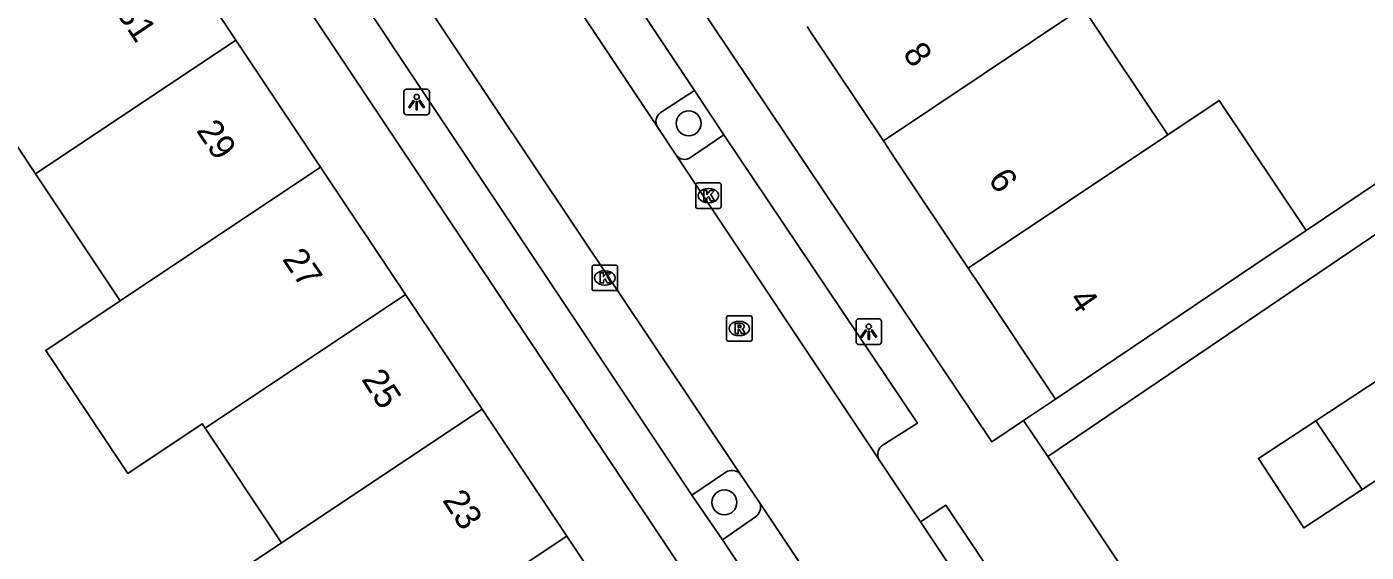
# Model space of a CAD drawing. Extents: x 158352 to 159489, y 383828 to 384597.
# Drawn here: x 158720.9 to 158773.4, y 384288.8 to 384309.4 of the extents above; entities that cross this region are included whole.
import ezdxf

# ---------------------------------------------------------------- set-up
doc = ezdxf.new("R2010")
doc.units = 0
for name, color, linetype in [('IMGEO_Boom', 7, 'Continuous'), ('IMGEO_Kolk', 7, 'Continuous'), ('IMGEO_Lichtpunt', 7, 'Continuous'), ('IMGEO_Pand', 7, 'Continuous'), ('IMGEO_Pand_nummerreeks', 7, 'Continuous'), ('IMGEO_Parkeervlak_open', 7, 'Continuous'), ('IMGEO_Rijbaan_lokaal_open', 7, 'Continuous'), ('IMGEO_Rioolput', 7, 'Continuous'), ('IMGEO_Voetpad_open', 7, 'Continuous')]:
    doc.layers.add(name, color=color, linetype=linetype)

msp = doc.modelspace()

# ---------------------------------------------------------------- linework, layer by layer
at = {"layer": 'IMGEO_Boom'}
for centre in [(158746.856, 384305.642), (158748.26, 384290.777)]:
    msp.add_circle(centre, 0.489, dxfattribs=at)
at = {"layer": 'IMGEO_Kolk'}
for p, q in [((158747.131, 384302.381), (158747.131, 384303.233)), ((158747.206, 384303.307), (158748.058, 384303.307)), ((158747.619, 384303.087), (158747.644, 384303.087)), ((158748.132, 384303.233), (158748.132, 384302.381)), ((158747.642, 384302.527), (158747.617, 384302.527)), ((158748.058, 384302.307), (158747.206, 384302.307)), ((158743.067, 384299.155), (158743.067, 384300.007)), ((158743.142, 384300.081), (158743.994, 384300.081)), ((158743.555, 384299.861), (158743.58, 384299.861)), ((158744.068, 384300.007), (158744.068, 384299.155)), ((158743.578, 384299.301), (158743.553, 384299.301)), ((158743.994, 384299.081), (158743.142, 384299.081))]:
    msp.add_line(p, q, dxfattribs=at)
for points in [[(158747.131, 384302.381), (158747.131, 384303.233)], [(158747.206, 384303.307), (158748.058, 384303.307)], [(158747.452, 384303.007), (158747.575, 384303.007), (158747.575, 384302.856), (158747.705, 384303.007), (158747.869, 384303.007), (158747.723, 384302.856), (158747.876, 384302.607), (158747.724, 384302.607), (158747.639, 384302.771), (158747.575, 384302.704), (158747.575, 384302.607), (158747.452, 384302.607), (158747.452, 384303.007)], [(158748.132, 384303.233), (158748.132, 384302.381)], [(158748.058, 384302.307), (158747.206, 384302.307)], [(158743.067, 384299.155), (158743.067, 384300.007)], [(158743.142, 384300.081), (158743.994, 384300.081)], [(158743.388, 384299.781), (158743.511, 384299.781), (158743.511, 384299.63), (158743.641, 384299.781), (158743.805, 384299.781), (158743.659, 384299.63), (158743.812, 384299.381), (158743.66, 384299.381), (158743.575, 384299.545), (158743.511, 384299.478), (158743.511, 384299.381), (158743.388, 384299.381), (158743.388, 384299.781)], [(158744.068, 384300.007), (158744.068, 384299.155)], [(158743.994, 384299.081), (158743.142, 384299.081)]]:
    msp.add_lwpolyline(points, dxfattribs=at)
for centre, start, end in [((158747.208, 384303.231), 91.552, 178.448), ((158747.208, 384303.231), 91.552, 178.448), ((158748.056, 384303.231), 1.552, 88.448), ((158748.056, 384303.231), 1.552, 88.448), ((158747.208, 384302.383), 181.552, 268.448), ((158747.208, 384302.383), 181.552, 268.448), ((158748.056, 384302.383), 271.552, 358.448), ((158748.056, 384302.383), 271.552, 358.448), ((158743.144, 384300.005), 91.552, 178.448), ((158743.144, 384300.005), 91.552, 178.448), ((158743.992, 384300.005), 1.552, 88.448), ((158743.992, 384300.005), 1.552, 88.448), ((158743.144, 384299.157), 181.552, 268.448), ((158743.144, 384299.157), 181.552, 268.448), ((158743.992, 384299.157), 271.552, 358.448), ((158743.992, 384299.157), 271.552, 358.448)]:
    msp.add_arc(centre, 0.0765, start, end, dxfattribs=at)
for centre, major_axis, ratio, start_param, end_param in [((158747.618, 384302.807), (-0.387, 0.002), 0.722429, 4.712389, 7.853982), ((158747.643, 384302.807), (-0.39, 0.002), 0.717154, 1.570796, 4.712389), ((158743.554, 384299.581), (-0.387, 0.002), 0.722429, 4.712389, 7.853982), ((158743.579, 384299.581), (-0.39, 0.002), 0.717154, 1.570796, 4.712389)]:
    msp.add_ellipse(centre, major_axis=major_axis, ratio=ratio, start_param=start_param, end_param=end_param, dxfattribs=at)
at = {"layer": 'IMGEO_Lichtpunt'}
for p, q in [((158735.688, 384306.881), (158735.688, 384306.074)), ((158735.688, 384306.881), (158735.688, 384306.074)), ((158736.59, 384306.976), (158735.782, 384306.976)), ((158736.59, 384306.976), (158735.782, 384306.976)), ((158736.684, 384306.074), (158736.684, 384306.881)), ((158736.684, 384306.074), (158736.684, 384306.881)), ((158735.782, 384305.98), (158736.59, 384305.98)), ((158735.782, 384305.98), (158736.59, 384305.98)), ((158753.424, 384297.875), (158753.424, 384297.068)), ((158753.424, 384297.875), (158753.424, 384297.068)), ((158754.326, 384297.97), (158753.518, 384297.97)), ((158754.326, 384297.97), (158753.518, 384297.97)), ((158754.42, 384297.068), (158754.42, 384297.875)), ((158754.42, 384297.068), (158754.42, 384297.875)), ((158753.518, 384296.974), (158754.326, 384296.974)), ((158753.518, 384296.974), (158754.326, 384296.974))]:
    msp.add_line(p, q, dxfattribs=at)
for points in [[(158736.062, 384306.545), (158736.101, 384306.517), (158735.913, 384306.255), (158735.875, 384306.282), (158736.062, 384306.545)], [(158736.274, 384306.517), (158736.312, 384306.544), (158736.499, 384306.282), (158736.46, 384306.254), (158736.274, 384306.517)], [(158736.164, 384306.497), (158736.211, 384306.497), (158736.211, 384306.175), (158736.164, 384306.175), (158736.164, 384306.497)], [(158753.798, 384297.539), (158753.837, 384297.511), (158753.649, 384297.249), (158753.611, 384297.276), (158753.798, 384297.539)], [(158753.9, 384297.491), (158753.947, 384297.491), (158753.947, 384297.169), (158753.9, 384297.169), (158753.9, 384297.491)], [(158754.01, 384297.511), (158754.048, 384297.538), (158754.235, 384297.276), (158754.196, 384297.248), (158754.01, 384297.511)]]:
    msp.add_lwpolyline(points, dxfattribs=at)
for centre in [(158736.187, 384306.679), (158753.923, 384297.673)]:
    msp.add_circle(centre, 0.0994, dxfattribs=at)
for centre, start, end in [((158735.782, 384306.881), 90, 180), ((158735.782, 384306.881), 90, 180), ((158736.59, 384306.881), 0, 90), ((158736.59, 384306.881), 0, 90), ((158735.782, 384306.074), 180, 270), ((158735.782, 384306.074), 180, 270), ((158736.59, 384306.074), 270, 0), ((158736.59, 384306.074), 270, 360), ((158753.518, 384297.875), 90, 180), ((158753.518, 384297.875), 90, 180), ((158754.326, 384297.875), 0, 90), ((158754.326, 384297.875), 0, 90), ((158753.518, 384297.068), 180, 270), ((158753.518, 384297.068), 180, 270), ((158754.326, 384297.068), 270, 0), ((158754.326, 384297.068), 270, 360)]:
    msp.add_arc(centre, 0.0946, start, end, dxfattribs=at)
at = {"layer": 'IMGEO_Pand'}
for points in [[(158729.096, 384308.902), (158726.098, 384313.399)], [(158754.497, 384304.952), (158762.322, 384310.18)], [(158762.322, 384310.18), (158762.786, 384309.485), (158763.459, 384308.478), (158765.656, 384305.19)], [(158754.497, 384304.952), (158751.64, 384309.236), (158751.501, 384309.445)], [(158721.235, 384303.662), (158729.096, 384308.902)], [(158732.416, 384303.922), (158729.096, 384308.902)], [(158718.236, 384308.158), (158721.235, 384303.662)], [(158765.656, 384305.19), (158767.669, 384306.535), (158771.074, 384301.44)], [(158765.656, 384305.19), (158757.826, 384299.96)], [(158757.826, 384299.96), (158754.961, 384304.256), (158754.497, 384304.952)], [(158732.416, 384303.922), (158724.556, 384298.683)], [(158735.745, 384298.927), (158732.416, 384303.922)], [(158724.556, 384298.683), (158721.235, 384303.662)], [(158771.074, 384301.44), (158769.065, 384300.088), (158761.248, 384294.829)], [(158761.248, 384294.829), (158758.282, 384299.276), (158757.826, 384299.96)], [(158724.556, 384298.683), (158721.636, 384296.735), (158724.854, 384291.911), (158727.774, 384293.858), (158727.887, 384293.689)], [(158735.745, 384298.927), (158727.887, 384293.689)], [(158738.751, 384294.436), (158735.745, 384298.927)], [(158771.454, 384293.979), (158773.978, 384295.637), (158775.767, 384292.914), (158773.276, 384291.278)], [(158730.885, 384289.193), (158738.751, 384294.436)], [(158742.072, 384289.458), (158738.751, 384294.436)], [(158773.276, 384291.278), (158770.991, 384289.777), (158769.202, 384292.5), (158771.454, 384293.979)], [(158771.454, 384293.979), (158773.276, 384291.278)], [(158727.887, 384293.689), (158730.885, 384289.193)], [(158742.072, 384289.458), (158734.206, 384284.214)], [(158745.403, 384284.464), (158742.072, 384289.458)], [(158730.885, 384289.193), (158727.536, 384286.959), (158730.857, 384281.98), (158734.206, 384284.214)]]:
    msp.add_lwpolyline(points, dxfattribs=at)
at = {"layer": 'IMGEO_Parkeervlak_open'}
for points in [[(158747.086, 384306.935), (158745.743, 384306.049)], [(158746.928, 384304.308), (158748.237, 384305.189)], [(158746.983, 384291.062), (158748.314, 384291.963)], [(158748.187, 384289.313), (158749.479, 384290.214)]]:
    msp.add_lwpolyline(points, dxfattribs=at)
for centre, radius, start, end in [((158745.981, 384305.718), 0.407, 125.7199, 209.4283), ((158746.691, 384304.624), 0.395, 214.8862, 306.8855), ((158748.557, 384291.554), 0.476, 49.3617, 120.7167), ((158749.226, 384290.589), 0.452, 303.9569, 18.1768)]:
    msp.add_arc(centre, radius, start, end, dxfattribs=at)
at = {"layer": 'IMGEO_Rijbaan_lokaal_open'}
for points in [[(158745.626, 384305.518), (158731.636, 384326.508)], [(158748.867, 384291.915), (158732.619, 384316.209)], [(158745.626, 384305.518), (158746.367, 384304.398)], [(158746.367, 384304.398), (158754.327, 384292.451)], [(158754.327, 384292.451), (158755.951, 384290.012)], [(158749.656, 384290.73), (158748.867, 384291.915)], [(158765.371, 384267.168), (158749.656, 384290.73)], [(158755.951, 384290.012), (158759.379, 384284.871)]]:
    msp.add_lwpolyline(points, dxfattribs=at)
at = {"layer": 'IMGEO_Rioolput'}
for p, q in [((158748.34, 384297.169), (158748.34, 384298.021)), ((158748.415, 384298.095), (158749.267, 384298.095)), ((158748.828, 384297.875), (158748.853, 384297.875)), ((158749.341, 384298.021), (158749.341, 384297.169)), ((158749.267, 384297.095), (158748.415, 384297.095)), ((158748.851, 384297.315), (158748.826, 384297.315))]:
    msp.add_line(p, q, dxfattribs=at)
for points in [[(158748.34, 384297.169), (158748.34, 384298.021)], [(158748.415, 384298.095), (158749.267, 384298.095)], [(158748.929, 384297.793), (158748.677, 384297.795), (158748.677, 384297.395)], [(158748.855, 384297.714), (158748.801, 384297.714), (158748.801, 384297.633)], [(158748.801, 384297.633), (158748.853, 384297.633)], [(158749.341, 384298.021), (158749.341, 384297.169)], [(158749.267, 384297.095), (158748.415, 384297.095)], [(158748.677, 384297.395), (158748.801, 384297.395), (158748.801, 384297.557), (158748.812, 384297.557)], [(158748.859, 384297.528), (158748.93, 384297.395), (158749.07, 384297.395), (158749.005, 384297.521)]]:
    msp.add_lwpolyline(points, dxfattribs=at)
for centre, radius, start, end in [((158748.417, 384298.019), 0.0765, 91.552, 178.448), ((158748.417, 384298.019), 0.0765, 91.552, 178.448), ((158748.837, 384297.822), 0.19, 274.7715, 282.9687), ((158748.861, 384297.618), 0.0964, 77.0061, 93.1865), ((158748.875, 384297.675), 0.0378, 276.6634, 79.6772), ((158748.928, 384297.683), 0.109, 350.3612, 89.416), ((158748.926, 384297.683), 0.112, 277.5842, 350.9817), ((158749.265, 384298.019), 0.0765, 1.552, 88.448), ((158749.265, 384298.019), 0.0765, 1.552, 88.448), ((158748.417, 384297.171), 0.0765, 181.552, 268.448), ((158748.417, 384297.171), 0.0765, 181.552, 268.448), ((158748.811, 384297.504), 0.0533, 26.0293, 88.6989), ((158748.91, 384297.468), 0.108, 29.5134, 73.7905), ((158749.265, 384297.171), 0.0765, 271.552, 358.448), ((158749.265, 384297.171), 0.0765, 271.552, 358.448)]:
    msp.add_arc(centre, radius, start, end, dxfattribs=at)
for centre, major_axis, ratio, start_param, end_param in [((158748.827, 384297.595), (-0.387, 0.002), 0.722429, 4.712389, 7.853982), ((158748.852, 384297.595), (-0.39, 0.002), 0.717154, 1.570796, 4.712389)]:
    msp.add_ellipse(centre, major_axis=major_axis, ratio=ratio, start_param=start_param, end_param=end_param, dxfattribs=at)
at = {"layer": 'IMGEO_Voetpad_open'}
for points in [[(158759.994, 384293.99), (158758.742, 384293.153), (158732.447, 384332.379)], [(158733.516, 384327.301), (158747.086, 384306.935)], [(158721.854, 384325.255), (158761.364, 384266.025), (158758.812, 384264.322)], [(158760.941, 384292.573), (158779.118, 384304.891), (158781.507, 384304.689), (158806.635, 384321.537)], [(158731.136, 384314.846), (158746.983, 384291.062)], [(158778.401, 384309.181), (158779.708, 384307.248), (158771.074, 384301.44)], [(158747.086, 384306.935), (158748.237, 384305.189)], [(158748.237, 384305.189), (158755.828, 384293.879), (158754.48, 384293.033)], [(158761.248, 384294.829), (158759.994, 384293.99)], [(158760.941, 384292.573), (158759.994, 384293.99)], [(158777.399, 384267.966), (158761.047, 384292.415), (158760.941, 384292.573)], [(158746.983, 384291.062), (158748.187, 384289.313)], [(158755.951, 384290.012), (158756.941, 384290.664), (158760.598, 384285.21)], [(158748.187, 384289.313), (158763.493, 384266.393), (158764.827, 384267.282)]]:
    msp.add_lwpolyline(points, dxfattribs=at)
msp.add_arc((158754.731, 384292.656), 0.453, 123.6891, 206.8529, dxfattribs=at)

# ---------------------------------------------------------------- texts
at = {"layer": 'IMGEO_Pand_nummerreeks'}
for s, rotation, p in [('31', 303.8316, (158724.379, 384309.979)), ('8', 304.5434, (158755.23, 384308.38)), ('29', 303.6052, (158727.519, 384305.363)), ('6', 303.7585, (158758.578, 384303.452)), ('27', 304.1366, (158730.889, 384300.314)), ('4', 304.807, (158761.741, 384298.734)), ('25', 302.7631, (158734, 384295.605)), ('23', 302.9792, (158737.175, 384290.862))]:
    msp.add_text(s, height=1, rotation=rotation, dxfattribs=at).set_placement(p)

doc.saveas('drawing.dxf')
